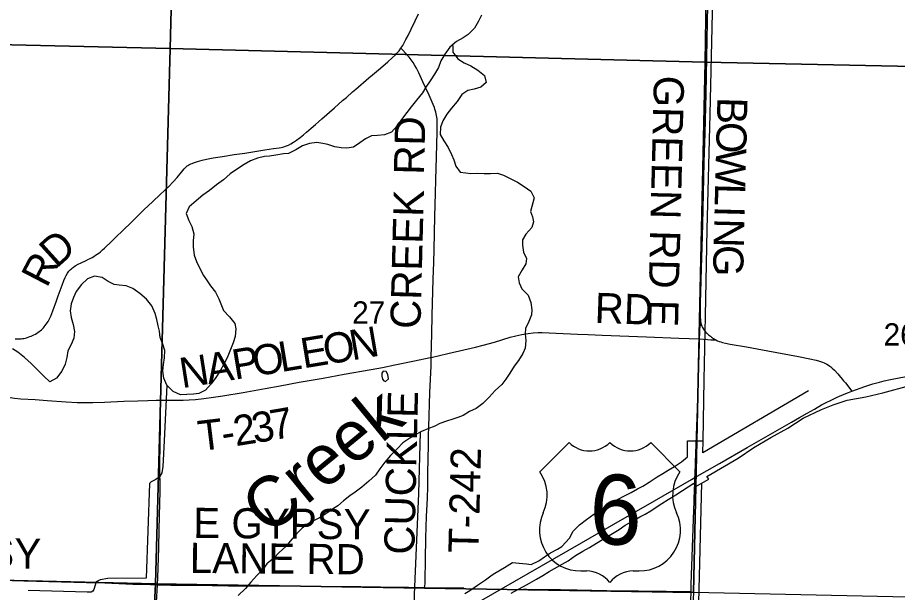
# Model space of a CAD drawing. Extents: x -59 to 43, y 0 to 22.
# Drawn here: x 27.989 to 29.644, y 16.205 to 17.288 of the extents above; entities that cross this region are included whole.
import ezdxf

# ---------------------------------------------------------------- set-up
doc = ezdxf.new("R2010")
doc.units = 0
for name, color, linetype in [('GM_X_County_Road', 7, 'Continuous'), ('GM_X_County_Road_Text', 7, 'Continuous'), ('GM_X_Major_River', 7, 'Continuous'), ('GM_X_Minor_Lake', 7, 'Continuous'), ('GM_X_Minor_River', 7, 'Continuous'), ('GM_X_Minor_River_Text', 7, 'Continuous'), ('GM_X_Section', 7, 'Continuous'), ('GM_X_Section_Text', 7, 'Continuous'), ('GM_X_Township_Road', 7, 'Continuous'), ('GM_X_Township_Road_Text', 7, 'Continuous'), ('GM_X_US_Location', 7, 'Continuous'), ('GM_X_US_Route', 7, 'Continuous'), ('GM_X_US_Shield', 7, 'Continuous')]:
    doc.layers.add(name, color=color, linetype=linetype)

msp = doc.modelspace()

# ---------------------------------------------------------------- linework, layer by layer
at = {"layer": 'GM_X_County_Road'}
for points in [[(29.287, 17.4123), (29.2873, 17.4116), (29.2881, 17.408), (29.2886, 17.4043), (29.2887, 17.3993), (29.2884, 17.3701), (29.2867, 17.2806), (29.2839, 17.1445), (29.282, 17.0705), (29.2804, 17.0158), (29.2774, 16.8984), (29.2763, 16.8561), (29.2751, 16.8157), (29.2741, 16.7704), (29.2734, 16.7499), (29.2731, 16.7238), (29.2736, 16.7182), (29.274, 16.7156), (29.2745, 16.7126), (29.2751, 16.7106)], [(29.2751, 16.7106), (29.2756, 16.709), (29.2766, 16.7066), (29.2779, 16.7043), (29.2795, 16.7013), (29.281, 16.6991), (29.2827, 16.6968), (29.2841, 16.6951), (29.2856, 16.6936), (29.2871, 16.6921), (29.2888, 16.6906), (29.2905, 16.6892), (29.2924, 16.6877), (29.2944, 16.6862), (29.2962, 16.6849), (29.2982, 16.6836), (29.303, 16.6808)], [(29.303, 16.6808), (29.3058, 16.6794), (29.3088, 16.6781), (29.3119, 16.6771), (29.315, 16.6763), (29.3207, 16.6749), (29.3299, 16.673), (29.3605, 16.6676), (29.4003, 16.6603), (29.4583, 16.6494), (29.4797, 16.6452), (29.4918, 16.6426), (29.4978, 16.6411), (29.5036, 16.6391), (29.5064, 16.638), (29.5092, 16.6367), (29.5118, 16.6352), (29.5144, 16.6336), (29.5169, 16.6318), (29.5193, 16.63), (29.5217, 16.628), (29.5261, 16.6237), (29.5323, 16.6168), (29.5431, 16.6042)], [(27.8602, 16.6215), (27.8724, 16.6152), (27.894, 16.6042), (27.9174, 16.5926), (27.9291, 16.587), (27.9377, 16.5833), (27.9469, 16.5799), (27.9581, 16.5762), (27.9647, 16.5745), (27.9713, 16.5732), (27.983, 16.5715), (27.9947, 16.5703), (28.022, 16.5686), (28.0443, 16.5671), (28.0803, 16.5643), (28.1008, 16.5632), (28.1132, 16.5629), (28.1306, 16.5631), (28.1523, 16.5638), (28.189, 16.5654), (28.2151, 16.5664), (28.2337, 16.567), (28.2499, 16.5674), (28.2577, 16.5675)], [(29.5431, 16.6042), (29.5464, 16.6002), (29.5584, 16.5845)], [(28.2521, 16.2199), (28.2528, 16.2335), (28.2547, 16.2894), (28.2553, 16.3237), (28.2568, 16.3734), (28.2571, 16.3952), (28.2568, 16.4449), (28.2569, 16.4853), (28.2575, 16.5164), (28.2579, 16.5412), (28.258, 16.5534), (28.258, 16.5569), (28.2577, 16.5675)], [(27.6327, 16.2362), (27.6377, 16.2359), (27.6687, 16.2343), (27.709, 16.2326), (27.74, 16.2316), (27.7556, 16.2314), (27.768, 16.2315), (27.7897, 16.2323), (27.8052, 16.2325), (27.83, 16.2322), (27.8642, 16.2312), (27.9355, 16.2294), (28.0007, 16.2274), (28.1186, 16.2244), (28.1527, 16.2233), (28.2055, 16.2213), (28.2388, 16.2203), (28.2521, 16.2199)], [(28.2384, 15.9442), (28.2394, 15.9602), (28.2411, 15.9912), (28.2435, 16.0378), (28.2447, 16.0627), (28.2476, 16.1217), (28.2505, 16.1869), (28.2521, 16.2199)]]:
    msp.add_lwpolyline(points, dxfattribs=at)
at = {"layer": 'GM_X_Major_River'}
for points in [[(28.8615, 17.2927), (28.856, 17.2814), (28.8489, 17.2682), (28.8369, 17.2563), (28.8273, 17.2496), (28.8147, 17.2426), (28.8023, 17.2322), (28.7929, 17.2191), (28.7855, 17.2067), (28.7811, 17.1939), (28.7736, 17.1815), (28.7651, 17.1687), (28.7572, 17.1567), (28.7506, 17.1465), (28.7393, 17.1323), (28.7292, 17.12), (28.721, 17.1095), (28.7113, 17.0963), (28.7031, 17.0843), (28.6926, 17.0724), (28.6792, 17.0673), (28.6659, 17.0656), (28.6549, 17.0654), (28.6434, 17.0596), (28.633, 17.0518), (28.6207, 17.044), (28.6081, 17.042), (28.5979, 17.0425), (28.5861, 17.0446), (28.5729, 17.0487), (28.563, 17.0511), (28.552, 17.0525), (28.5383, 17.0508), (28.525, 17.0465), (28.5123, 17.0388), (28.4989, 17.0318), (28.4893, 17.0312), (28.4745, 17.0288), (28.463, 17.0267), (28.4535, 17.0265), (28.4402, 17.0233), (28.4272, 17.0182), (28.4149, 17.0112), (28.4026, 17.0031), (28.3891, 16.9939), (28.376, 16.9823), (28.3629, 16.9727), (28.3498, 16.9626), (28.3374, 16.9534), (28.3251, 16.943), (28.312, 16.9318), (28.306, 16.919), (28.3108, 16.906), (28.3166, 16.8945), (28.3202, 16.8807), (28.3192, 16.8675), (28.319, 16.8561), (28.321, 16.8408), (28.3253, 16.8286), (28.3315, 16.8156), (28.3389, 16.8025), (28.3456, 16.7925), (28.3519, 16.7829), (28.3615, 16.7706), (28.3678, 16.7583), (28.371, 16.7488), (28.3765, 16.7361), (28.3877, 16.7245), (28.3977, 16.7118), (28.3994, 16.7015), (28.398, 16.6875), (28.3948, 16.6754), (28.3884, 16.6596), (28.3829, 16.6471), (28.3769, 16.6351), (28.3699, 16.6227)], [(28.3699, 16.6227), (28.3617, 16.6103), (28.3531, 16.5983), (28.3422, 16.5863), (28.3296, 16.5801), (28.3201, 16.5787), (28.3071, 16.5782), (28.2953, 16.5777), (28.2814, 16.5836), (28.2694, 16.5956), (28.2643, 16.6086), (28.2623, 16.6223), (28.2633, 16.6345), (28.265, 16.6473), (28.2657, 16.661), (28.2621, 16.6728), (28.257, 16.6855), (28.2557, 16.6976), (28.2536, 16.7076), (28.2508, 16.7194), (28.2476, 16.7308), (28.2417, 16.745), (28.2313, 16.7577), (28.219, 16.7686), (28.2058, 16.7779), (28.193, 16.7827), (28.1801, 16.7841), (28.1706, 16.7854), (28.1593, 16.7909), (28.1477, 16.7987), (28.1333, 16.8013), (28.1207, 16.7958), (28.1091, 16.7854), (28.0989, 16.7723), (28.0938, 16.761), (28.0894, 16.7489), (28.0877, 16.736), (28.0897, 16.723), (28.0933, 16.7097), (28.0957, 16.6971), (28.0947, 16.6842), (28.0899, 16.6721), (28.0836, 16.6601), (28.0815, 16.648), (28.0786, 16.6351), (28.0723, 16.6219), (28.0618, 16.6088), (28.0495, 16.6018), (28.0383, 16.6126), (28.0264, 16.6246), (28.0144, 16.6366), (28.0021, 16.6479), (27.989, 16.6576), (27.9792, 16.6642)]]:
    msp.add_lwpolyline(points, dxfattribs=at)
at = {"layer": 'GM_X_Minor_Lake'}
msp.add_line((28.6741, 16.6127), (28.6755, 16.6073), dxfattribs=at)
msp.add_lwpolyline([(28.6755, 16.6073), (28.6777, 16.6042), (28.6811, 16.6027), (28.6865, 16.6075), (28.6855, 16.6159), (28.6826, 16.6212), (28.6769, 16.6221), (28.6742, 16.6184), (28.6741, 16.6127)], dxfattribs=at)
at = {"layer": 'GM_X_Minor_River'}
for points in [[(29.4769, 16.5853), (29.278, 16.4685), (29.2788, 16.4912), (29.2809, 16.6059), (29.283, 16.7263), (29.2867, 16.8888), (29.2922, 17.106), (29.2967, 17.297), (29.2991, 17.512)], [(28.8081, 17.2352), (28.8078, 17.2226), (28.8175, 17.2103), (28.8291, 17.2029), (28.842, 17.197), (28.8551, 17.1891), (28.8671, 17.1786), (28.8703, 17.1657), (28.8606, 17.1567), (28.848, 17.1532), (28.8358, 17.1507), (28.8246, 17.1429), (28.816, 17.1298), (28.8056, 17.1174), (28.7966, 17.1058), (28.7888, 17.0934), (28.7848, 17.0813), (28.7838, 17.0677), (28.7908, 17.0558), (28.7989, 17.0431), (28.8051, 17.0301), (28.8095, 17.0201), (28.8135, 17.0079), (28.8216, 16.9967), (28.8322, 16.9954), (28.8417, 16.9945), (28.8539, 16.995), (28.8668, 16.9944), (28.8786, 16.9942), (28.8919, 16.9947), (28.9032, 16.9911), (28.9168, 16.984), (28.9296, 16.9777), (28.942, 16.9699), (28.9547, 16.9609), (28.961, 16.9486), (28.9541, 16.9229), (28.9577, 16.913), (28.9594, 16.9035), (28.9562, 16.8925), (28.9449, 16.8798), (28.939, 16.8696), (28.9389, 16.8594), (28.9409, 16.8464), (28.9464, 16.8342), (28.9454, 16.8239), (28.9384, 16.8127), (28.9309, 16.7999), (28.9326, 16.7885), (28.9377, 16.777), (28.9497, 16.765), (28.9548, 16.7512), (28.9564, 16.7379), (28.9559, 16.7284), (28.9507, 16.7156), (28.9448, 16.7024), (28.9442, 16.6925), (28.9455, 16.6796), (28.9437, 16.6656), (28.9397, 16.6554), (28.9311, 16.6419), (28.923, 16.6317), (28.9148, 16.6186), (28.9077, 16.6069), (28.9003, 16.5968), (28.8872, 16.5857), (28.8763, 16.5733), (28.8643, 16.561), (28.8516, 16.5517), (28.839, 16.5459), (28.827, 16.5389), (28.8175, 16.5349), (28.8079, 16.532), (28.7957, 16.528), (28.7834, 16.5233), (28.7739, 16.5186), (28.7608, 16.5135), (28.7486, 16.5084), (28.7367, 16.5025), (28.7267, 16.4958), (28.714, 16.487), (28.7028, 16.4758), (28.6908, 16.4634), (28.6799, 16.4507), (28.6702, 16.438), (28.662, 16.426), (28.65, 16.4148), (28.6369, 16.4036), (28.6238, 16.394), (28.6142, 16.3873), (28.6018, 16.3777), (28.5914, 16.3687), (28.5814, 16.3621), (28.5706, 16.3547), (28.5572, 16.3462), (28.5468, 16.341), (28.5365, 16.3355), (28.5245, 16.3262), (28.5137, 16.3158), (28.5017, 16.302), (28.4935, 16.2922)], [(28.2694, 16.5956), (28.2645, 16.4912), (28.2621, 16.4426), (28.2604, 16.4305), (28.2561, 16.423), (28.2488, 16.4182), (28.2399, 16.4134), (28.2372, 16.4108), (28.231, 16.2323), (28.1584, 16.2318), (28.1443, 16.229), (28.137, 16.2253), (28.1346, 16.2193), (28.1322, 16.2109), (28.1306, 16.2079), (28.1271, 16.2061), (28.1199, 16.2058), (28.009, 16.209)], [(29.2613, 16.4112), (29.2639, 16.4041), (29.2893, 16.4189), (29.2859, 16.4235), (29.3447, 16.4585), (29.3739, 16.4785), (29.4062, 16.4973), (29.4384, 16.5146), (29.4669, 16.5338), (29.5014, 16.5499), (29.5236, 16.5586), (29.55, 16.5673), (29.585, 16.5739), (29.6167, 16.5813), (29.6679, 16.5948)], [(28.7463, 16.5073), (28.7431, 16.3915), (28.7351, 16.2013), (28.734, 16.1435)], [(29.2497, 16.4606), (29.2491, 16.4906), (29.2788, 16.4912)], [(28.8301, 16.2034), (28.8397, 16.2093), (28.854, 16.2189), (28.8693, 16.2293), (28.8817, 16.2385), (28.8868, 16.2415), (28.9052, 16.2522), (28.9201, 16.2618), (28.9329, 16.2604), (28.9463, 16.259), (28.955, 16.2582), (28.9696, 16.2651), (28.9806, 16.2725), (28.9919, 16.2799), (29.0047, 16.287), (29.0132, 16.292), (29.0273, 16.3073), (29.0344, 16.3205), (29.0464, 16.3328), (29.0595, 16.3425), (29.0734, 16.3525), (29.0857, 16.3599), (29.0983, 16.3672), (29.1079, 16.3739), (29.1179, 16.3802), (29.131, 16.3875), (29.1433, 16.3938), (29.1556, 16.4008), (29.1655, 16.4055), (29.1774, 16.4133), (29.1921, 16.4229), (29.2028, 16.4296), (29.2132, 16.4358), (29.2247, 16.4428), (29.2378, 16.4513), (29.2497, 16.4606)], [(29.2758, 16.4111), (29.2668, 16.0607), (29.2602, 15.8629), (29.2576, 15.7178), (29.2541, 15.6689), (29.2271, 15.6682), (28.8017, 15.6823), (28.5871, 15.6892), (28.2393, 15.703)], [(28.9175, 16.2041), (28.9302, 16.2111), (28.9406, 16.2166), (28.9521, 16.2228), (28.9651, 16.2302), (28.9774, 16.2376), (28.989, 16.2446), (28.9993, 16.2505), (29.0135, 16.2586), (29.025, 16.2652), (29.0385, 16.2752), (29.0527, 16.2833), (29.065, 16.2903), (29.0942, 16.308), (29.1084, 16.3165), (29.1211, 16.3239), (29.1323, 16.332), (29.1469, 16.3401), (29.1599, 16.3475), (29.1695, 16.3527), (29.1806, 16.3593), (29.1906, 16.3659), (29.2014, 16.3726), (29.2133, 16.3807), (29.2275, 16.3892), (29.2402, 16.3973), (29.2613, 16.4112)], [(28.4935, 16.2922), (28.4811, 16.2807), (28.4707, 16.2702), (28.4579, 16.2591), (28.4502, 16.2489), (28.4389, 16.2374), (28.4277, 16.2246), (28.4176, 16.2131), (28.4037, 16.1996)]]:
    msp.add_lwpolyline(points, dxfattribs=at)
at = {"layer": 'GM_X_Section'}
for points in [[(28.3019, 18.2312), (28.2762, 17.2295), (27.273, 17.253), (27.2918, 18.2449), (27.8326, 18.2227)], [(28.3019, 18.2312), (29.2974, 18.199), (29.2824, 17.2037), (28.2762, 17.2295)], [(29.2974, 18.199), (30.3019, 18.1906), (30.2784, 17.1834), (29.2824, 17.2037)], [(27.273, 17.253), (28.2762, 17.2295), (28.2485, 16.2218), (27.2374, 16.2454)], [(28.2762, 17.2295), (29.2824, 17.2037), (29.2609, 16.2051), (28.2485, 16.2218)], [(29.2824, 17.2037), (30.2784, 17.1834), (30.2413, 16.1837), (29.2609, 16.2051)], [(27.2374, 16.2454), (28.2485, 16.2218), (28.1989, 15.2189), (27.2112, 15.2343), (27.2021, 15.2348)], [(29.2609, 16.2051), (29.207, 15.2007), (28.2121, 15.218), (28.1989, 15.2189), (28.2485, 16.2218)]]:
    msp.add_lwpolyline(points, close=True, dxfattribs=at)
at = {"layer": 'GM_X_Township_Road'}
for points in [[(28.7102, 17.2303), (28.7137, 17.2356), (28.7176, 17.2426), (28.7196, 17.2465), (28.7235, 17.2543), (28.7292, 17.266), (28.7368, 17.2821), (28.7431, 17.2951)], [(27.9842, 16.6827), (27.9892, 16.6827), (27.9923, 16.6828), (27.9953, 16.683), (27.9979, 16.6833), (28.0004, 16.6838), (28.0032, 16.6844), (28.0057, 16.6851), (28.009, 16.6861), (28.0122, 16.6872), (28.0145, 16.6881), (28.0168, 16.6892), (28.0197, 16.6905), (28.0224, 16.692), (28.0248, 16.6934), (28.0271, 16.6949), (28.0293, 16.6965), (28.0316, 16.6983), (28.0338, 16.7002), (28.0357, 16.702), (28.0373, 16.7038), (28.0391, 16.7057), (28.041, 16.7081), (28.0429, 16.7106), (28.0447, 16.7133), (28.0463, 16.7158), (28.0477, 16.7184), (28.0489, 16.7208), (28.0502, 16.7234), (28.0512, 16.7258), (28.0551, 16.7357), (28.0619, 16.7544), (28.0653, 16.7637), (28.0726, 16.7842), (28.0758, 16.793), (28.0783, 16.7987), (28.0804, 16.8025), (28.083, 16.8067), (28.0855, 16.8103), (28.0883, 16.8133), (28.0903, 16.8151), (28.0921, 16.8166), (28.0939, 16.818), (28.0973, 16.8203), (28.1027, 16.8233), (28.1083, 16.8262), (28.1178, 16.8307), (28.122, 16.8327), (28.1256, 16.8345), (28.129, 16.8363), (28.1322, 16.8381), (28.1356, 16.8403), (28.1384, 16.8422), (28.1415, 16.8445), (28.1448, 16.8471), (28.1485, 16.8503), (28.1523, 16.8537), (28.1662, 16.867), (28.1733, 16.8739), (28.1877, 16.8879), (28.2023, 16.9021), (28.2151, 16.9148), (28.2262, 16.9257), (28.2431, 16.9413), (28.2574, 16.9549), (28.2733, 16.97), (28.2814, 16.9785), (28.2889, 16.9869), (28.2971, 16.997), (28.3022, 17.0032), (28.3053, 17.0063), (28.3069, 17.0076), (28.3082, 17.0087), (28.3095, 17.0095), (28.3108, 17.0104), (28.3126, 17.0114), (28.3147, 17.0123), (28.3172, 17.0134), (28.3198, 17.0145), (28.3237, 17.0158), (28.3275, 17.0171), (28.3316, 17.0183), (28.3359, 17.0195), (28.3443, 17.0214), (28.3566, 17.0237), (28.3744, 17.0265), (28.3965, 17.0298), (28.4162, 17.0329), (28.4543, 17.0386), (28.4703, 17.0411), (28.4813, 17.0429), (28.4846, 17.0434), (28.4873, 17.044), (28.4899, 17.0447), (28.4932, 17.0457), (28.4983, 17.0478), (28.5033, 17.0503), (28.5082, 17.0531), (28.5138, 17.057), (28.5203, 17.0619), (28.527, 17.0674), (28.5327, 17.0722), (28.5412, 17.0795), (28.5492, 17.0864), (28.5548, 17.0913), (28.5613, 17.0971), (28.5852, 17.1179), (28.6005, 17.1315), (28.6075, 17.1377), (28.6193, 17.1478), (28.6254, 17.1531), (28.6498, 17.1743), (28.6564, 17.18), (28.6678, 17.1897), (28.6806, 17.2005), (28.6858, 17.2049), (28.6937, 17.2119), (28.6991, 17.2171), (28.7021, 17.2202), (28.7066, 17.2254), (28.7102, 17.2303)], [(28.7672, 16.6481), (28.7681, 16.6927), (28.7689, 16.727), (28.7709, 16.7954), (28.7719, 16.8265), (28.7724, 16.8514), (28.7739, 16.9136), (28.7749, 16.9572), (28.7756, 16.9821), (28.7769, 17.0256), (28.7784, 17.0723), (28.7786, 17.0816), (28.7784, 17.091), (28.7781, 17.0973), (28.7773, 17.1035), (28.776, 17.1097), (28.7742, 17.1157), (28.7731, 17.1187), (28.7707, 17.1244), (28.7632, 17.1416), (28.7516, 17.1671), (28.7437, 17.184), (28.7395, 17.1924), (28.7364, 17.1979), (28.7331, 17.2032), (28.7296, 17.2083), (28.7257, 17.2133), (28.7196, 17.2204), (28.7132, 17.2272), (28.7102, 17.2303)], [(29.2722, 16.6829), (29.2723, 16.6948), (29.2728, 16.7011), (29.2735, 16.7055), (29.2741, 16.7081), (29.2751, 16.7106)], [(28.7672, 16.6481), (28.7987, 16.6551), (28.8507, 16.6673), (28.8651, 16.6711), (28.886, 16.677), (28.9158, 16.686), (28.9261, 16.6887), (28.9377, 16.6911), (28.9494, 16.693), (28.9587, 16.694), (28.9681, 16.6946), (28.9762, 16.6947), (29.0023, 16.6938), (29.0426, 16.6919), (29.0625, 16.691), (29.0886, 16.69), (29.1725, 16.6868), (29.2333, 16.6844), (29.2722, 16.6829)], [(29.2634, 16.4216), (29.2636, 16.4278), (29.2645, 16.4502), (29.2657, 16.4843), (29.2669, 16.5179), (29.2681, 16.5514), (29.2719, 16.6751), (29.2722, 16.6829)], [(29.2722, 16.6829), (29.2869, 16.6817), (29.2936, 16.6814), (29.303, 16.6808)], [(28.2577, 16.5675), (28.2722, 16.5677), (28.3002, 16.5675), (28.312, 16.5679), (28.3237, 16.5687), (28.3391, 16.5705), (28.3576, 16.5729), (28.3753, 16.5759), (28.4134, 16.582), (28.455, 16.5893), (28.4832, 16.5944), (28.5186, 16.6011), (28.5639, 16.6091), (28.6036, 16.6165), (28.6544, 16.6255), (28.6752, 16.6293), (28.699, 16.6339), (28.7355, 16.6413), (28.7653, 16.6476), (28.7672, 16.6481)], [(28.762, 16.5018), (28.7624, 16.5165), (28.7648, 16.5818), (28.7668, 16.6316), (28.7671, 16.644), (28.7672, 16.6481)], [(28.7545, 16.215), (28.7551, 16.218), (28.7557, 16.2216), (28.7558, 16.2271), (28.7564, 16.2676), (28.7572, 16.3081), (28.7585, 16.3485), (28.7599, 16.3827), (28.7606, 16.4045), (28.7609, 16.4294), (28.7614, 16.4574), (28.7619, 16.4823), (28.762, 16.4978), (28.762, 16.5018)], [(29.2562, 16.207), (29.2565, 16.221), (29.2587, 16.2899), (29.2609, 16.3433), (29.262, 16.3769), (29.2628, 16.4024), (29.2629, 16.4067), (29.2632, 16.4185), (29.2634, 16.4216)], [(28.2521, 16.2199), (28.2584, 16.2197), (28.2771, 16.2193), (28.3082, 16.2189), (28.3548, 16.2183), (28.3858, 16.2181), (28.42, 16.2178), (28.4511, 16.2179), (28.5008, 16.2177), (28.5443, 16.2174), (28.5754, 16.2169), (28.6345, 16.2163), (28.6717, 16.2157), (28.7028, 16.2155), (28.7246, 16.2153), (28.7545, 16.215)], [(28.7545, 16.215), (28.7556, 16.2149), (28.7991, 16.2142), (28.8267, 16.2138), (28.8286, 16.2138)], [(28.9417, 16.2119), (28.9471, 16.2118), (28.9788, 16.2112), (29.0105, 16.2108), (29.0416, 16.2102), (29.0974, 16.2093), (29.1572, 16.2084), (29.2092, 16.2076), (29.2362, 16.2072), (29.2508, 16.2071), (29.2562, 16.207)], [(29.2426, 15.6837), (29.2424, 15.6903), (29.2424, 15.7021), (29.2438, 15.7425), (29.2459, 15.8146), (29.2476, 15.8786), (29.2486, 15.9171), (29.2499, 15.9681), (29.2505, 15.9948), (29.2521, 16.0569), (29.2528, 16.0892), (29.2532, 16.1054), (29.2552, 16.1719), (29.2562, 16.207)]]:
    msp.add_lwpolyline(points, dxfattribs=at)
at = {"layer": 'GM_X_US_Route'}
for points in [[(29.5521, 16.582), (29.5584, 16.5845), (29.5833, 16.5935), (29.598, 16.5982), (29.6104, 16.6015), (29.6196, 16.6037), (29.6311, 16.6062), (29.6476, 16.6093), (29.6678, 16.6131), (29.6805, 16.6151), (29.6954, 16.6167), (29.7112, 16.6178), (29.7241, 16.6185), (29.7381, 16.6189), (29.7535, 16.6194), (29.7643, 16.6192), (29.7753, 16.6189), (29.7902, 16.6183)], [(28.8165, 16.1643), (28.9248, 16.2267), (29.0499, 16.2986), (29.1107, 16.3337), (29.1872, 16.3778), (29.2567, 16.4178), (29.2634, 16.4216), (29.3093, 16.4482), (29.3614, 16.4781), (29.3926, 16.4958), (29.4229, 16.5135), (29.4448, 16.526), (29.4604, 16.5351), (29.4746, 16.5432), (29.4881, 16.5508), (29.5017, 16.5584), (29.5091, 16.5622), (29.5197, 16.5676), (29.5313, 16.5731), (29.5476, 16.5802), (29.5521, 16.582)]]:
    msp.add_lwpolyline(points, dxfattribs=at)
at = {"layer": 'GM_X_US_Shield'}
for p, q in [((29.0265, 16.4876), (28.9715, 16.4327)), ((29.2352, 16.4327), (29.1803, 16.4876)), ((29.0484, 16.2459), (29.0594, 16.2459)), ((29.1473, 16.2459), (29.1583, 16.2459))]:
    msp.add_line(p, q, dxfattribs=at)
for centre, radius, start, end in [((29.0649, 16.5269), 0.0549, 225.573, 314.427), ((29.1418, 16.5269), 0.0549, 225.573, 314.427), ((28.9085, 16.3886), 0.0769, 334.5471, 35.0009), ((29.2982, 16.3886), 0.0769, 144.9991, 205.4529), ((29.0476, 16.3228), 0.0769, 154.8319, 270.6383), ((29.1592, 16.3228), 0.0769, 269.3617, 25.1681), ((29.0594, 16.191), 0.0549, 36.8699, 90), ((29.1473, 16.191), 0.0549, 90, 143.1301)]:
    msp.add_arc(centre, radius, start, end, dxfattribs=at)

# ---------------------------------------------------------------- texts
at = {"layer": 'GM_X_County_Road_Text'}
for s, height, rotation, p in [('GREEN RD E', 0.05682, 268.5855, (29.1864, 17.1791)), ('B', 0.0568, 268.5245, (29.3057, 17.1386)), ('O', 0.0568, 268.5245, (29.3045, 17.092)), ('W', 0.0568, 268.5252, (29.3032, 17.042)), ('L', 0.0568, 268.5256, (29.3015, 16.9762)), ('I', 0.0568, 268.5246, (29.3005, 16.9337)), ('N', 0.0568, 268.5268, (29.2999, 16.9103)), ('G', 0.0568, 268.6901, (29.2986, 16.8602)), ('E GYPSY', 0.05682, 359.0373, (27.6992, 16.2556))]:
    msp.add_text(s, height=height, rotation=rotation, dxfattribs=at).set_placement(p)
at = {"layer": 'GM_X_Minor_River_Text'}
msp.add_text('Creek', height=0.09475, rotation=39.3954, dxfattribs=at).set_placement((28.4611, 16.3107))
at = {"layer": 'GM_X_Section_Text'}
for s, p in [('27', (28.6184, 16.7117)), ('26', (29.6184, 16.6704))]:
    msp.add_text(s, height=0.04186, rotation=0, dxfattribs=at).set_placement(p)
at = {"layer": 'GM_X_Township_Road_Text'}
for s, height, rotation, p in [('RD', 0.05682, 88.5613, (28.7535, 16.9915)), ('CREEK', 0.05682, 88.5305, (28.7468, 16.7012)), ('D', 0.0568, 42.0235, (28.062, 16.8146)), ('R', 0.0568, 62.5238, (28.0438, 16.7774)), ('RD', 0.05682, 358.0636, (29.074, 16.7131)), ('N', 0.0568, 9.6742, (28.6182, 16.6423)), ('E', 0.0568, 9.3757, (28.5266, 16.6272)), ('O', 0.0568, 9.3776, (28.5685, 16.6341)), ('O', 0.0568, 9.3743, (28.4353, 16.6121)), ('L', 0.0568, 9.3781, (28.4847, 16.6203)), ('A', 0.0568, 9.3754, (28.3482, 16.5978)), ('P', 0.0568, 9.3775, (28.3975, 16.6059)), ('N', 0.0568, 8.8509, (28.2982, 16.59)), ('CUCKLE', 0.05682, 88.6341, (28.7352, 16.2761)), ('2', 0.0568, 9.1642, (28.3994, 16.4807)), ('3', 0.0568, 9.2016, (28.434, 16.4863)), ('7', 0.0568, 9.6438, (28.469, 16.492)), ('T', 0.0568, 6.9081, (28.3318, 16.4716)), ('-', 0.0568, 9.0811, (28.3763, 16.477)), ('T-242', 0.05682, 88.5975, (28.8561, 16.2793)), ('E GYPSY', 0.05682, 359.5054, (28.3192, 16.3081)), ('LANE RD', 0.05682, 359.5246, (28.3126, 16.2421))]:
    msp.add_text(s, height=height, rotation=rotation, dxfattribs=at).set_placement(p)
at = {"layer": 'GM_X_US_Location'}
for s in ['0', '/']:
    msp.add_text(s, height=0.000189, dxfattribs=at).set_placement((29.1033, 16.3603))
msp.add_text('6', height=0.000189, rotation=0, dxfattribs=at).set_placement((29.0842, 16.3211))
at = {"layer": 'GM_X_US_Shield'}
msp.add_text('6', height=0.1318, dxfattribs=at).set_placement((29.0651, 16.2954))

doc.saveas('drawing.dxf')
